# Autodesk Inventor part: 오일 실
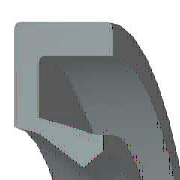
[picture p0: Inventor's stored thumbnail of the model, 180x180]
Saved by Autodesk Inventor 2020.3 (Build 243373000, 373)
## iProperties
Created: 2012-02
Part Number: 오일 실
Material: 고무
Description: 오일 실 - 스프링 장착, 비스프링, 고무 덮개 G
Document SubType Name: Modeling
Standard: JIS B 2402
Designer: mduedu
Standards Organization: JIS
Language: ko-KR
Size Designation: 20 32 5 A
Categories: <MemberInstance><Categories><Category DisplayName="샤프트 부품" InternalName="7f7aeb1f-a693-4053-b835-cee3144e0d98" Mnemonic="SHFT"><Category DisplayName="실링" Intern
Density: 0.93 g/cm^3
Appearance: 고무 - 검은색 - 버전 1.1
IsCustomPart: 1
Author: mduedu
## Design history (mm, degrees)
body "Solid1"
revolve "회전1" stored, may be unused: angle "d29" = 360 deg
chamfer "모따기1" distance "d30" = 0.25 (= 0.05 x b); stored, may be unused: second distance "d31" = 0.5 (= 0.1 x b), angle "d39" = 45 deg
chamfer "모따기2" distance "d32" = 0.5 (= 0.1 x b); stored, may be unused: second distance "d33" = 0.25 (= 0.05 x b), angle "d40" = 45 deg
fillet "모깎기1" dims "d34" = 0.25 (= 0.05 x b)
sketch "스케치2"
  geometry: L1 (10.997, -3.438)-(11.297, -5); L2 (10.597, -3.282)-(10.997, -3.438); L3 (10, -1.72)-(10.597, -3.282); L4 (11.091, -1.22)-(10, -1.72); L5 (12.133, -3.75)-(11.091, -1.22); L6 (13.333, -3.75)-(12.133, -3.75); L7 (14.667, -1.25)-(13.333, -3.75); L8 (14.667, 0)-(14.667, -1.25); L9 (16, 0)-(14.667, 0); L10 (16, -5)-(16, 0); L11 (11.297, -5)-(16, -5); L12 (0, -9.6)-(0, 1.6) reference; L13 (28, 0)-(14, 0) reference
  constraints: 22 end point, 3 horizontal, 2 vertical
  dimensions: "d2" = 5 distance of L10.start L9.start (= b); "d4" = 1.25 vertical distance of L5.start L1.end (= 0.25 x b); "d6" = 1.33333 distance of L9.start L8.start (= 0.111111 x dd - 0.111111 x Diam); "d8" = 1.25 distance of L8.start L7.start (= 0.25 x b); "d10" = 1.33333 horizontal distance of L7.start L6.start (= 0.111111 x dd - 0.111111 x Diam); "d12" = 1.21951 vertical distance of L9.start L4.start (= 0.243902 x b); "d14" = 1.09091 horizontal distance of L4.start L3.start (= 0.0909091 x dd - 0.0909091 x Diam); "d16" = 0.5 vertical distance of L4.start L3.start (= 0.1 x b); "d18" = 1.2 distance of L6.start L5.start (= 0.1 x dd - 0.1 x Diam); "d20" = 1.5625 vertical distance of L3.start L2.start (= 0.3125 x b); "d22" = 0.59701 horizontal distance of L3.start L2.start (= 0.0497512 x dd - 0.0497512 x Diam); "d24" = 0.3 horizontal distance of L1.start L1.end (= 0.025 x dd - 0.025 x Diam); "d26" = 1.5625 vertical distance of L1.start L1.end (= 0.3125 x b); "d28" = 0.4 horizontal distance of L2.start L1.start (= 0.0333333 x dd - 0.0333333 x Diam); "d35" = 0 distance between parallel lines of L13 L9; "d36" = 16 distance between parallel lines of L12 L10 (= 0.5 x dd); "d37" = 10 distance from line of L12 L3.start (= 0.5 x Diam)
other parameters: "dd" = 32 [user parameter; used in 8 equation terms], "b" = 5 [user parameter; used in 12 equation terms], "d1" = 8 (derived), "d3" = 2 (derived), "d5" = 2.22222 (derived), "d7" = 2 (derived), "d9" = 2.22222 (derived), "d11" = 1.95122 (derived), "d13" = 1.81818 (derived), "d15" = 0.8 (derived), "d17" = 2 (derived), "d19" = 2.5 (derived), "d21" = 0.99502 (derived), "d23" = 0.5 (derived), "d25" = 2.5 (derived), "d27" = 0.66667 (derived), "d38" = 0
